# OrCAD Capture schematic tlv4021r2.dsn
size A
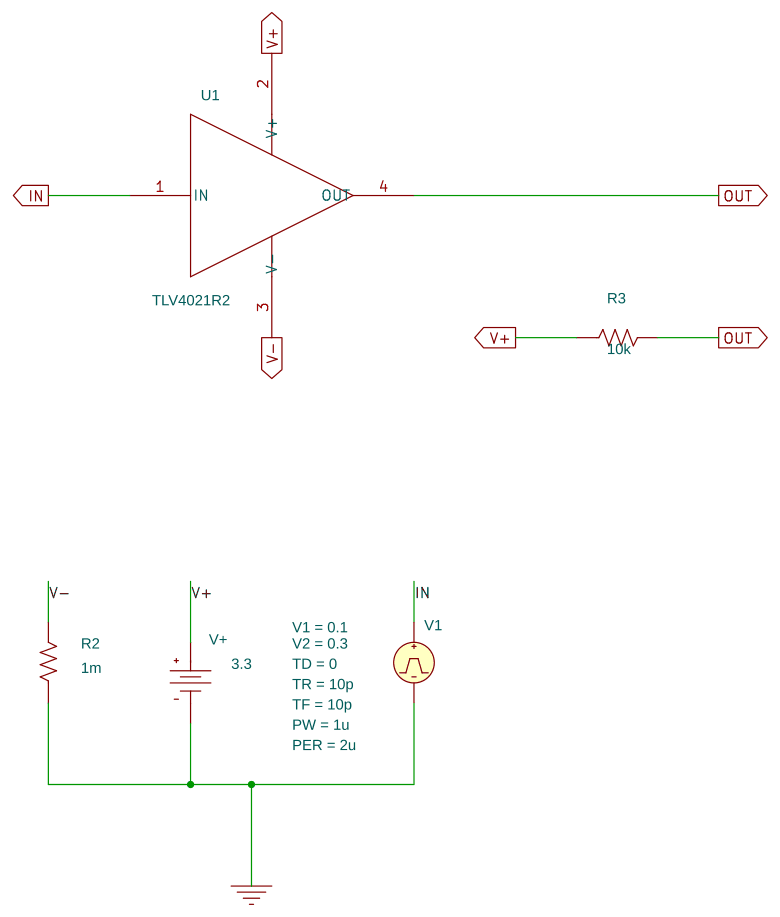
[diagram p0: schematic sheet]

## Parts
R2  1m  [AXRC05]
R3  10k  [AXRC05]
U1  TLV4021R2
V1  VPULSE
V+  VDC

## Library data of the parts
R2 R3 = R
U1 = TLV4021R2
V1 = VPULSE: PER: 2u; PW: 1u; TD: 0; TF: 10p; TR: 10p; V1: 0.1; V2: 0.3
V+ = VDC: DC: 3.3

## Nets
0: R2.1 V1.2(-) V+.1(-)
IN: U1.1(IN) V1.1(+)
OUT: R3.2 U1.4(OUT)
V+: R3.1 U1.2(V+) V+.0(+)
V-: R2.2 U1.3(V-)
